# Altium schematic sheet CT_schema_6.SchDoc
size 218 x 198 mm
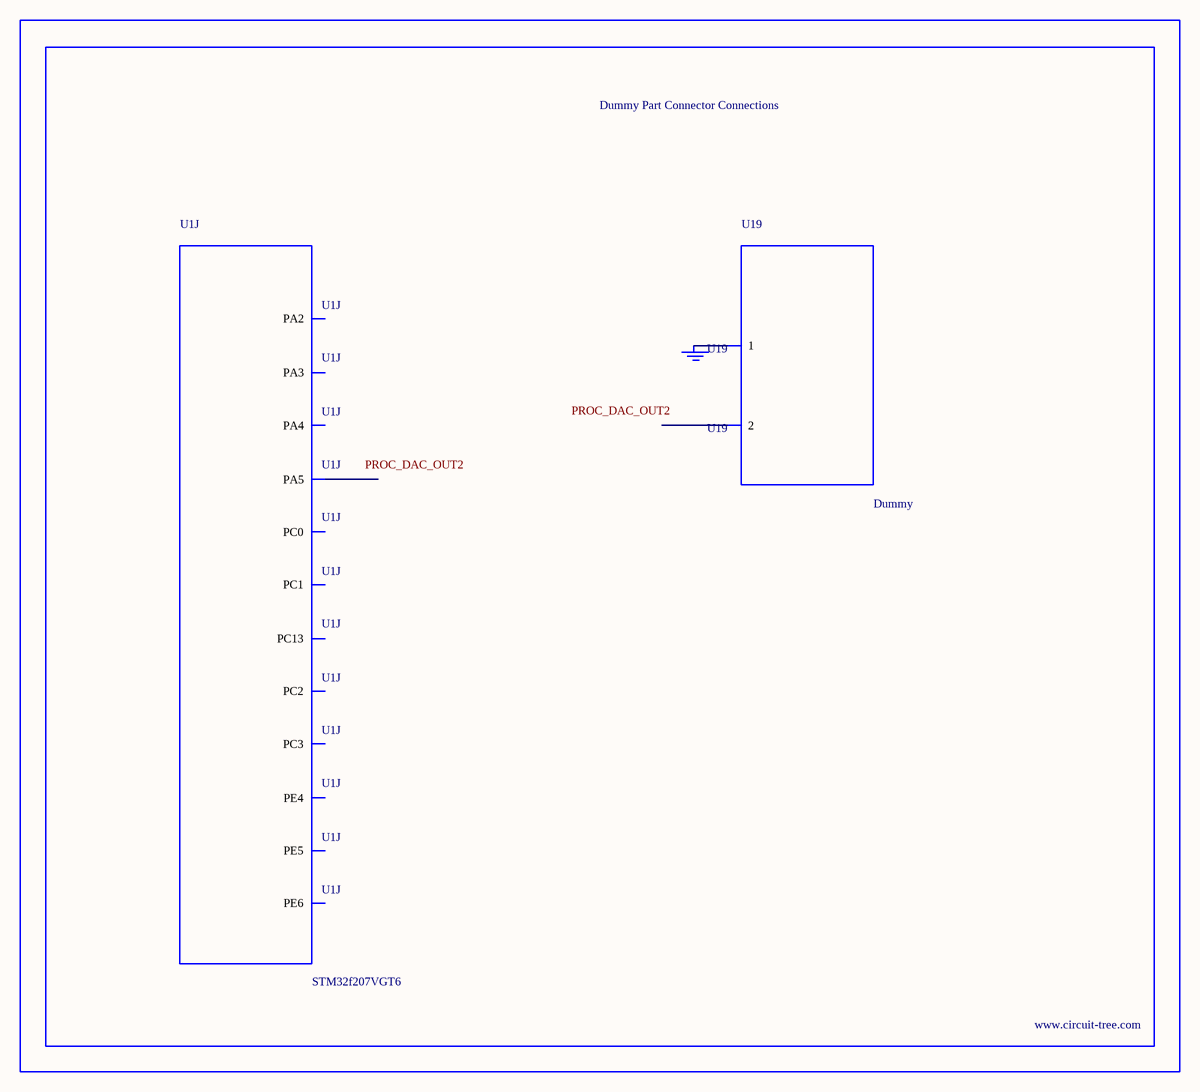
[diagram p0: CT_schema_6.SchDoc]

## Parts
BORDER5  (no value)
GND_INSTANCE_5_0  (no value)
U1  STM32f207VGT6  [LQFP100]  (part J of 10)
U19  Dummy  [DUMMY_PACKAGE_173]

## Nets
NetGND_INSTANCE_5_0_0: GND_INSTANCE_5_0.0(GND) U19.1

Not connected (* = marked no-connect by the designer): U1 3(PE4) 4(PE5) 5(PE6) 7(PC13) 15(PC0) 16(PC1) 17(PC2) 18(PC3) 25(PA2) 26(PA3) 29(PA4) 30(PA5); U19 2

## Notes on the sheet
- Labels drawn without touching a wire or pin: PROC_DAC_OUT2

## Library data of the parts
BORDER5 = BORDER_PAGE5
GND_INSTANCE_5_0 = GND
